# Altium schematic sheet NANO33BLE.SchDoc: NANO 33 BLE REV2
size A3; Date: 4/3/2020 11:51:50 AM; Author: Arturo Guadalupi; DocumentNumber: ABX00071/72; Revision: V6.3; SheetNumber: 1; SheetTotal: 1; Origin: Eagle; LibraryName: Arduino-utility; RevAuthor: Silvio Navaretti
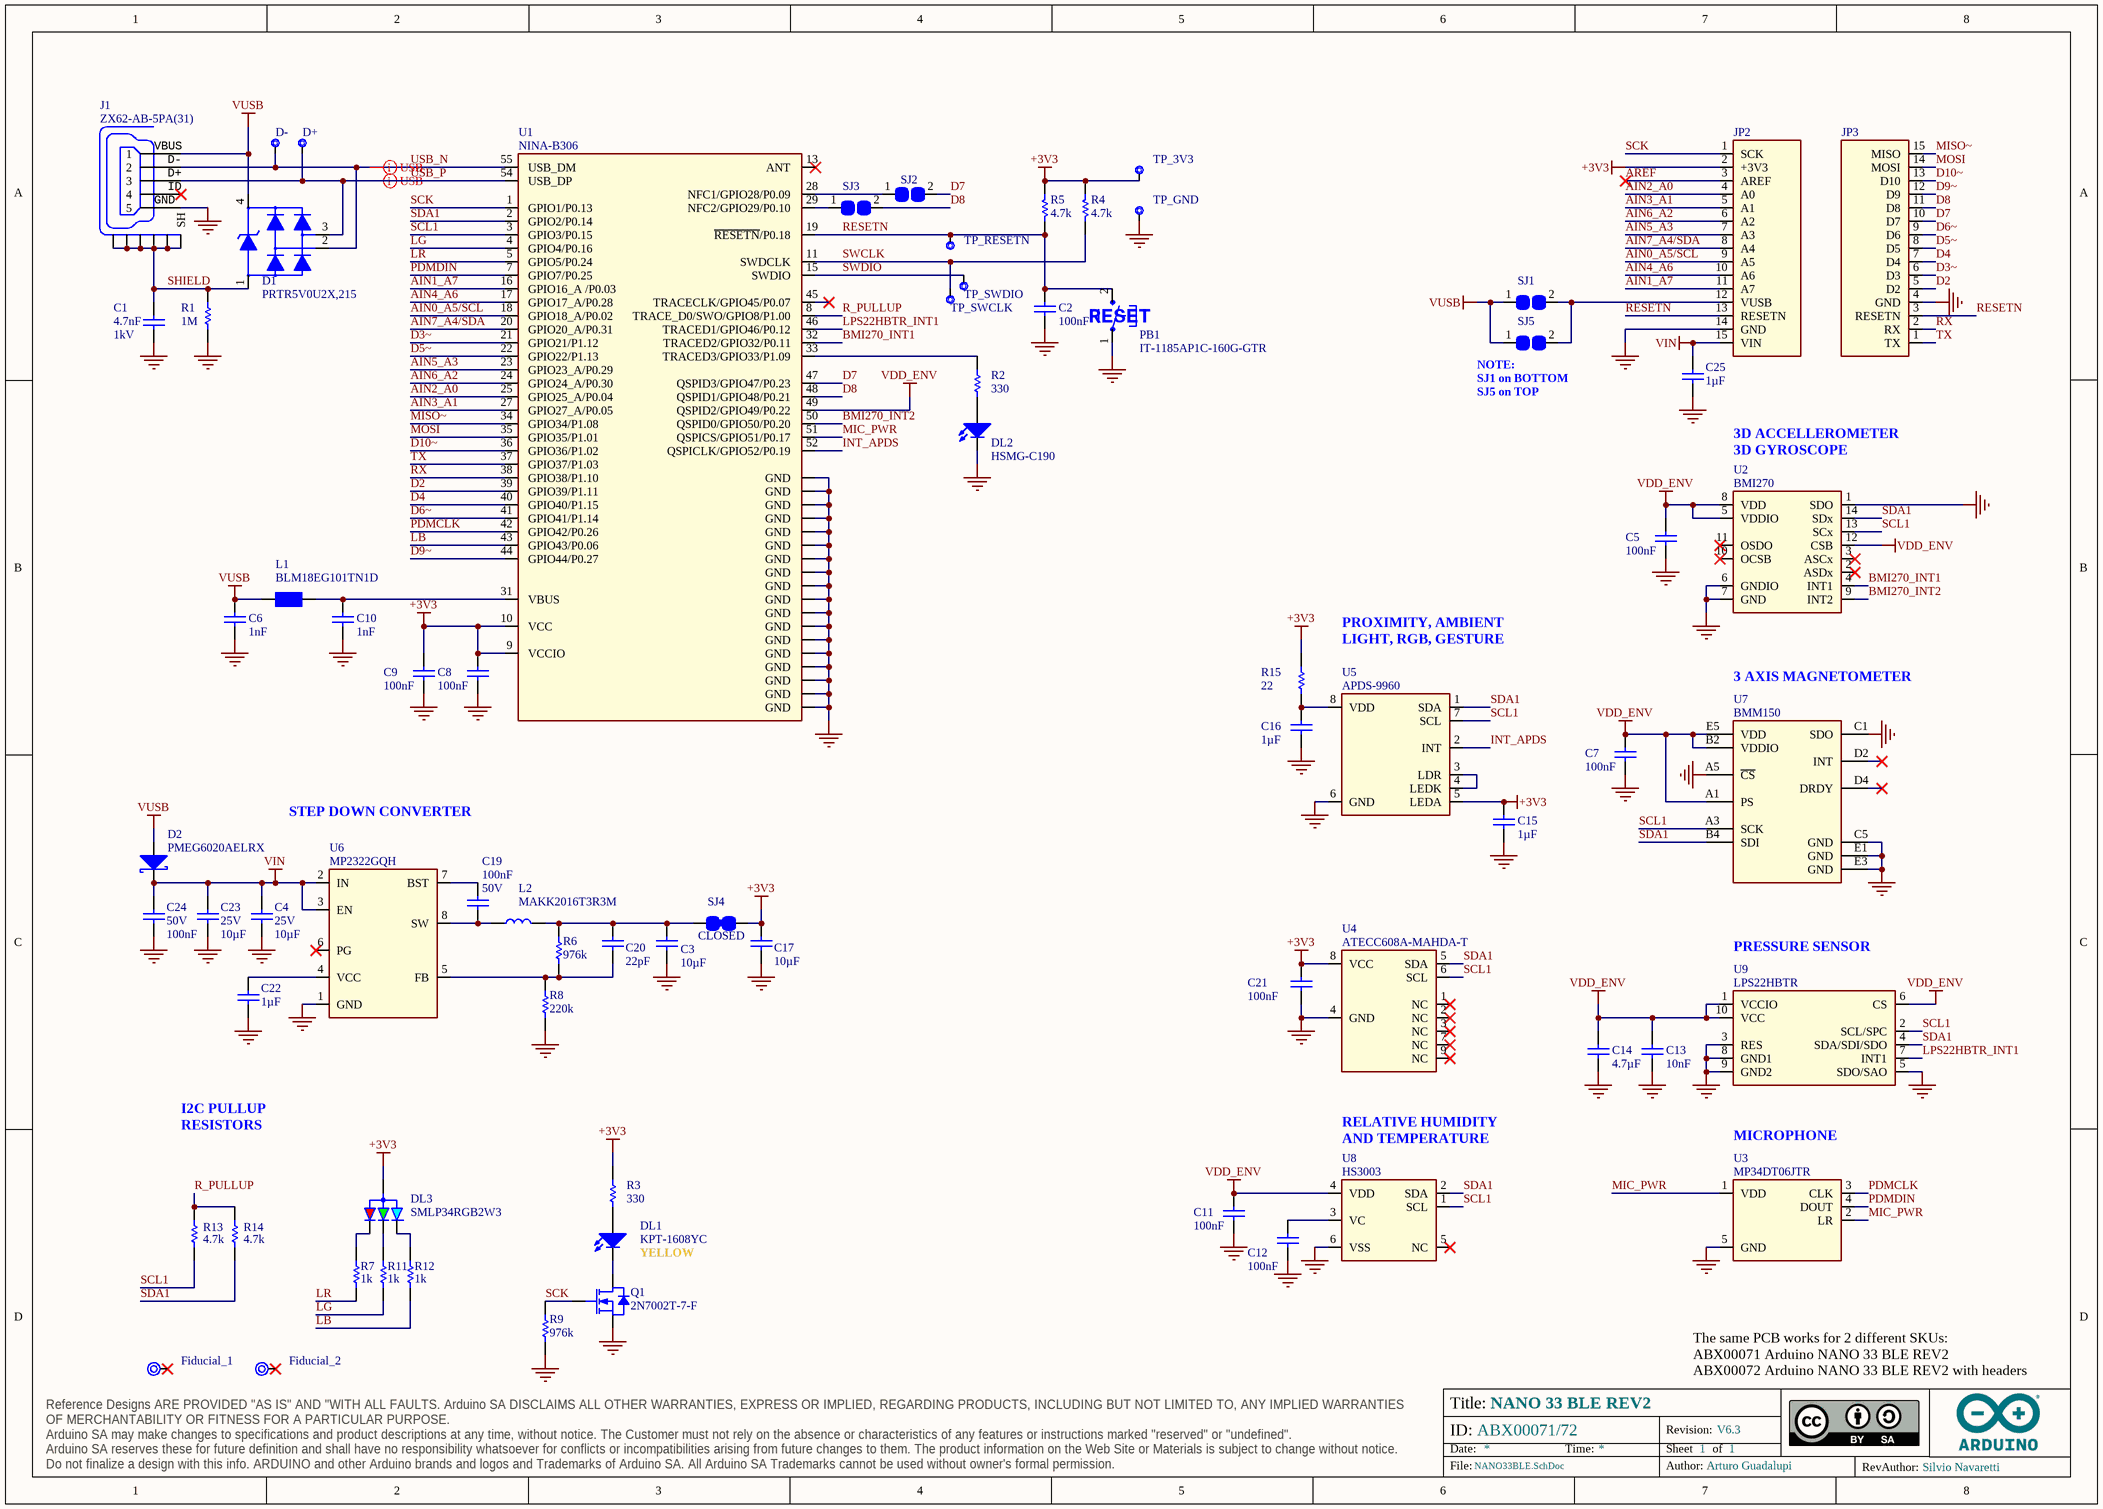
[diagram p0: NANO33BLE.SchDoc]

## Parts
C1  value 4.7nF  Voltage: 1kV  [CAP-0805]  (hidden comment: FV21X472K102ECG)
C2  value 100nF  [CAP-0402]  (hidden comment: GRM155R61H104KE19D)
C3  value 10µF  [CAP-0603]  (hidden comment: C1608A106M250NT)
C4  value 10µF  Voltage: 25V  [CAP-0603]  (hidden comment: C1608A106M250NT)
C5  value 100nF  [CAP-0402]  (hidden comment: 0402B104K160CT)
C6  value 1nF  [CAP-0402]  (hidden comment: GRM155R71H102KA01D)
C7  value 100nF  [CAP-0402]  (hidden comment: GRM155R61H104KE19D)
C8  value 100nF  [CAP-0402]  (hidden comment: GRM155R61H104KE19D)
C9  value 100nF  [CAP-0402]  (hidden comment: GRM155R61H104KE19D)
C10  value 1nF  [CAP-0402]  (hidden comment: GRM155R71H102KA01D)
C11  value 100nF  [CAP-0402]  (hidden comment: GRM155R61H104KE19D)
C12  value 100nF  [CAP-0402]  (hidden comment: GRM155R61H104KE19D)
C13  value 10nF  [CAP-0402]  (hidden comment: C1005B103K500NT)
C14  value 4.7µF  [CAP-0402]  (hidden comment: C1005A475M6R3NT)
C15  value 1µF  [CAP-0402]  (hidden comment: CL05A105KP5NNNC)
C16  value 1µF  [CAP-0402]  (hidden comment: CL05A105KP5NNNC)
C17  value 10µF  [CAP-0603]  (hidden comment: C1608A106M250NT)
C19  value 100nF  Voltage: 50V  [CAP-0402]  (hidden comment: GRM155R61H104KE19D)
C20  value 22pF  [CAP-0402]  (hidden comment: 0402N220J500CT)
C21  value 100nF  [CAP-0402]  (hidden comment: GRM155R61H104KE19D)
C22  value 1µF  [CAP-0402]  (hidden comment: CL05A105KP5NNNC)
C23  value 10µF  Voltage: 25V  [CAP-0603]  (hidden comment: C1608A106M250NT)
C24  value 100nF  Voltage: 50V  [CAP-0402]  (hidden comment: GRM155R61H104KE19D)
C25  value 1µF  [CAP-0402]  (hidden comment: CL05A105KP5NNNC)
D1  PRTR5V0U2X,215  [SOT190P230X110-4N]
D2  PMEG6020AELRX  [SOD123-1]
D+  CMP-018-0005-A.3  [TP-1.00MM]  (value not drawn)  (no BOM)
D-  CMP-018-0005-A.3  [TP-1.00MM]  (value not drawn)  (no BOM)
DL1  KPT-1608YC  [LEDC1608X80N-AK]
DL2  HSMG-C190  [LEDC1608X80N-AK]
DL3  SMLP34RGB2W3  [SMLP34RGB2W]
Fiducial_1  Fiducial mark 1mm with 2mm solder  [Fiducial mark 1mm with circle-Footprint-1]  (value not drawn)  (no BOM)
Fiducial_2  Fiducial mark 1mm with 2mm solder  [Fiducial mark 1mm with circle-Footprint-1]  (value not drawn)  (no BOM)
J1  ZX62-AB-5PA(31)  [ZX62-AB-5PA]
JP2  PINHD-1X15-NANO-ANALOG-CASTELLATED  [PINHD-1X14_5VF]  (value not drawn)
JP3  PINHD-1X15-NANO-DIGITAL-CASTELLATED  [PINHD-1X14_5VF]  (value not drawn)
L1  BLM18EG101TN1D  [L-0603]
L2  MAKK2016T3R3M  [MAKK2016T3R3M-Footprint-1]
PB1  IT-1185AP1C-160G-GTR  [C&K_PTS820_NO_HOLES-1]
Q1  2N7002T-7-F  [SOT523]
R1  value 1M  [RES-0402]  (hidden comment: CRCW04021M00FKED)
R2  value 330  [RES-0402]  (hidden comment: CRCW0402330RJNED)
R3  value 330  [RES-0402]  (hidden comment: CRCW0402330RJNED)
R4  value 4.7k  [RES-0402]  (hidden comment: RC0402FR-074K7L)
R5  value 4.7k  [RES-0402]  (hidden comment: RC0402FR-074K7L)
R6  value 976k  [RES-0402]  (hidden comment: CRCW0402976KFKED)
R7  value 1k  [RES-0402]  (hidden comment: CRCW04021K00FKEDC)
R8  value 220k  [RES-0402]  (hidden comment: CRCW0402220KFKED)
R9  value 976k  [RES-0402]  (hidden comment: CRCW0402976KFKED)
R11  value 1k  [RES-0402]  (hidden comment: CRCW04021K00FKEDC)
R12  value 1k  [RES-0402]  (hidden comment: CRCW04021K00FKEDC)
R13  value 4.7k  [RES-0402]  (hidden comment: RC0402FR-074K7L)
R14  value 4.7k  [RES-0402]  (hidden comment: RC0402FR-074K7L)
R15  value 22  [RES-0402]  (hidden comment: RC0402FR-0722RL)
SJ1  SMD solder JUMPER 0805  [SJ]  (value not drawn)
SJ2  SMD solder JUMPER 0805  [SJ]  (value not drawn)
SJ3  SMD solder JUMPER 0805  [SJ]  (value not drawn)
SJ4  SMD solder JUMPER CLOSED  [SJ]  (value not drawn)
SJ5  SMD solder JUMPER 0805  [SJ]  (value not drawn)
TP_3V3  CMP-018-0005-A.3  [TP-1.00MM]  (value not drawn)  (no BOM)
TP_GND  CMP-018-0005-A.3  [TP-1.00MM]  (value not drawn)  (no BOM)
TP_RESETN  CMP-018-0005-A.3  [TP-1.00MM]  (value not drawn)  (no BOM)
TP_SWCLK  CMP-018-0005-A.3  [TP-1.00MM]  (value not drawn)  (no BOM)
TP_SWDIO  CMP-018-0005-A.3  [TP-1.00MM]  (value not drawn)  (no BOM)
U1  NINA-B306  [NINA-B3X]
U2  BMI270  [VFLGA14]
U3  MP34DT06JTR  [HCLGA]
U4  ATECC608A-MAHDA-T  [UDFN8]
U5  APDS-9960  [APDS-9660-Footprint-1]
U6  MP2322GQH  [QFN50P150X200X90-8L]
U7  BMM150  [FP-BMM150-MFG]
U8  HS3003  [HS3003-Footprint-1]
U9  LPS22HBTR  [LPS22H]

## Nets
+3V3: C8.2 C9.1 C15.2 C17.2 C21.2 DL3.1(ANODE) JP2.2(+3V3) R3.2 R4.2 R5.2 R15.2 SJ4.2 TP_3V3.X U1.9(VCCIO) U1.10(VCC) U4.8(VCC) U5.5(LEDA)
GND: C1.1 C2.2 C3.1 C4.1 C5.2 C6.2 C7.1 C8.1 C9.2 C10.2 C11.2 C12.2 C13.2 C14.2 C15.1 C16.1 C17.1 C21.1 C22.1 C23.1 C24.2 C25.1 DL2.C J1.5 JP2.14(GND) JP3.4(GND) PB1.1 Q1.S R1.1 R8.1 R9.1 TP_GND.X U1.6(GND) U1.12(GND) U1.14(GND) U1.26(GND) U1.30(GND) U1.53(GND) U1.GND1(GND) U1.GND2(GND) U1.GND3(GND) U1.GND4(GND) U1.GND5(GND) U1.GND6(GND) U1.GND7(GND) U1.GND8(GND) U1.GND9(GND) U1.GND10(GND) U1.GND11(GND) U1.GND12(GND) U2.1(SDO) U2.6(GNDIO) U2.7(GND) U3.5(GND) U4.4(GND) U5.6(GND) U6.1(GND) U7.A5(~{CS}) U7.C1(SDO) U7.C5(GND) U7.E1(GND) U7.E3(GND) U8.6(VSS) U9.3(RES) U9.5(SDO/SAO) U9.8(GND1) U9.9(GND2)
VDD_ENV: C5.1 C7.2 C11.1 C13.1 C14.1 U1.49(QSPID2/GPIO49/P0.22) U2.5(VDDIO) U2.8(VDD) U2.12(CSB) U7.A1(PS) U7.B2(VDDIO) U7.E5(VDD) U8.4(VDD) U9.1(VCCIO) U9.6(CS) U9.10(VCC)
VIN: C4.2 C23.2 C24.1 C25.2 D2.C JP2.15(VIN) U6.2(IN) U6.3(EN)
VUSB: C6.1 D1.4 D2.A J1.1 L1.1 SJ1.1 SJ5.1
AIN0_A5/SCL: JP2.9(A5) U1.18(GPIO18_A/P0.02)
AIN1_A7: JP2.11(A7) U1.16(GPIO16_A_/P0.03)
AIN2_A0: JP2.4(A0) U1.25(GPIO25_A/P0.04)
AIN3_A1: JP2.5(A1) U1.27(GPIO27_A/P0.05)
AIN4_A6: JP2.10(A6) U1.17(GPIO17_A/P0.28)
AIN5_A3: JP2.7(A3) U1.23(GPIO23_A/P0.29)
AIN6_A2: JP2.6(A2) U1.24(GPIO24_A/P0.30)
AIN7_A4/SDA: JP2.8(A4) U1.20(GPIO20_A/P0.31)
AREF: JP2.3(AREF)
BMI270_INT1: U1.32(TRACED2/GPIO32/P0.11) U2.4(INT1)
BMI270_INT2: U1.50(QSPID0/GPIO50/P0.20) U2.9(INT2)
D2: JP3.5(D2) U1.39(GPIO39/P1.11)
D3~: JP3.6(D3) U1.21(GPIO21/P1.12)
D4: JP3.7(D4) U1.40(GPIO40/P1.15)
D5~: JP3.8(D5) U1.22(GPIO22/P1.13)
D6~: JP3.9(D6) U1.41(GPIO41/P1.14)
D7: JP3.10(D7) SJ2.2 U1.47(QSPID3/GPIO47/P0.23)
D8: JP3.11(D8) SJ3.2 U1.48(QSPID1/GPIO48/P0.21)
D9~: JP3.12(D9) U1.44(GPIO44/P0.27)
D10~: JP3.13(D10) U1.36(GPIO36/P1.02)
INT_APDS: U1.52(QSPICLK/GPIO52/P0.19) U5.2(INT)
LB: R12.1 U1.43(GPIO43/P0.06)
LG: R11.1 U1.4(GPIO4/P0.16)
LPS22HBTR_INT1: U1.46(TRACED1/GPIO46/P0.12) U9.7(INT1)
LR: R7.1 U1.5(GPIO5/P0.24)
MIC_PWR: U1.51(QSPICS/GPIO51/P0.17) U3.1(VDD) U3.2(LR)
MISO~: JP3.15(MISO) U1.34(GPIO34/P1.08)
MOSI: JP3.14(MOSI) U1.35(GPIO35/P1.01)
PDMCLK: U1.42(GPIO42/P0.26) U3.3(CLK)
PDMDIN: U1.7(GPIO7/P0.25) U3.4(DOUT)
R_PULLUP: R13.2 R14.2 U1.8(TRACE_D0/SWO/GPIO8/P1.00)
RESETN: C2.1 JP2.13(RESETN) JP3.3(RESETN) PB1.2 R5.1 TP_RESETN.X U1.19(~{RESETN}/P0.18)
RX: JP3.2(RX) U1.38(GPIO38/P1.10)
SCK: JP2.1(SCK) Q1.G R9.2 U1.1(GPIO1/P0.13)
SCL1: R13.1 U1.3(GPIO3/P0.15) U2.13(SCx) U4.6(SCL) U5.7(SCL) U7.A3(SCK) U8.1(SCL) U9.2(SCL/SPC)
SDA1: R14.1 U1.2(GPIO2/P0.14) U2.14(SDx) U4.5(SDA) U5.1(SDA) U7.B4(SDI) U8.2(SDA) U9.4(SDA/SDI/SDO)
SHIELD: C1.2 D1.1 J1.M1(SH) J1.M2(SH) J1.M3(SH) J1.M4(SH) J1.M5(SH) J1.M6(SH) R1.2
SWCLK: R4.1 TP_SWCLK.X U1.11(SWDCLK)
SWDIO: TP_SWDIO.X U1.15(SWDIO)
TX: JP3.1(TX) U1.37(GPIO37/P1.03)
USB_N: D1.2 D-.X J1.2 U1.55(USB_DM)
USB_P: D1.3 D+.X J1.3 U1.54(USB_DP)
NetC3_2: C3.2 C20.2 L2.2 R6.2 SJ4.1
NetC10_1: C10.1 L1.2 U1.31(VBUS)
NetC12_1: C12.1 U8.3(VC)
NetC16_2: C16.2 R15.1 U5.8(VDD)
NetC19_1: C19.1 L2.1 U6.8(SW)
NetC19_2: C19.2 U6.7(BST)
NetC20_1: C20.1 R6.1 R8.2 U6.5(FB)
NetC22_2: C22.2 U6.4(VCC)
NetDL1_A: DL1.A R3.1
NetDL1_C: DL1.C Q1.D
NetDL2_A: DL2.A R2.1
NetDL3_2: DL3.2(RED_C) R7.2
NetDL3_3: DL3.3(BLUE_C) R12.2
NetDL3_4: DL3.4(GREEN_C) R11.2
NetJP2_12: JP2.12(VUSB) SJ1.2 SJ5.2
NetR2_2: R2.2 U1.33(TRACED3/GPIO33/P1.09)
NetSJ2_1: SJ2.1 U1.28(NFC1/GPIO28/P0.09)
NetSJ3_1: SJ3.1 U1.29(NFC2/GPIO29/P0.10)
NetU5_3: U5.3(LDR) U5.4(LEDK)

Not connected (* = marked no-connect by the designer): Fiducial_1 1*; Fiducial_2 1*; J1 4*; U1 13(ANT)* 45(TRACECLK/GPIO45/P0.07)*; U2 2(ASDx)* 3(ASCx)* 10(OCSB)* 11(OSDO)*; U4 1(NC)* 2(NC)* 3(NC)* 7(NC)* 9(NC)*; U6 6(PG)*; U7 D2(INT)* D4(DRDY)*; U8 5(NC)*

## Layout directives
differential pair; differential pair class USB: USB_N, USB_P

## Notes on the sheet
- (near PB1) RESET
- (near SJ5) NOTE:
  SJ1 on BOTTOM
  SJ5 on TOP
- 3D ACCELLEROMETER
  3D GYROSCOPE
- PROXIMITY, AMBIENT LIGHT, RGB, GESTURE
- (near U7) 3 AXIS MAGNETOMETER
- STEP DOWN CONVERTER
- AUTHENTICATOR
- (near U9) PRESSURE SENSOR
- RGB LED
- SCK LED
- I2C PULLUP RESISTORS
- RELATIVE HUMIDITY
  AND TEMPERATURE
- MICROPHONE
- YELLOW
- The same PCB works for 2 different SKUs:
  ABX00071 Arduino NANO 33 BLE REV2
  ABX00072 Arduino NANO 33 BLE REV2 with headers

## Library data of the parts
C1 = C0059-A.14: CAP CHIP 0805 4.7nF 10% 1000V X7R; Manufacturer: PSA Shenzen; Code Arduino: 0689
C2 C7-C9 C11 C12 C19 C21 C24 = C0015-A.14: CAP CHIP 0402 100nF 10% 50V X5R; Manufacturer: Murata; Code Arduino: A5141
C3 C4 C17 C23 = C0047-A.18: CAP CHIP 0603 10uF 20% 25V X5R; Manufacturer: Hottech; Code Arduino: 2213
C5 = C0012-A.15: CAP CHIP 0402 100nF 10% 16V X7R; Manufacturer: Walsin; Code Arduino: 0132
C6 C10 = C0007-A.15: CAP CHIP 0402 1nF 10% 50V X7R; Manufacturer: KEMET; Code Arduino: 2321
C13 = C0009-A.15: CAP CHIP 0402 10nF 10% 50V X7R; Manufacturer: Hottech; Code Arduino: 0165
C14 = C0037-A.14: CAP CHIP 0402 4.7uF 20% 6V3 X5R; Manufacturer: Hottech; Code Arduino: 0833; Voltage: 6.3V
C15 C16 C22 C25 = C0017-A.14: CAP CHIP 0402 1uF 10% 10V X5R; Manufacturer: Samsung Electro-Mechanics; Code Arduino: 0133
C20 = C0029-A.14: CAP CHIP 0402 22pF 5% 50V C0G; Manufacturer: Walsin; Code Arduino: 0137
D1 = D0025-A.5: TVS ARRAY 4LIN.8kV 1pF SOT143B; Manufacturer: Nexperia; Device Type: ESD protection; Code Arduino: 2209
D2 = D0026-A.6: DIODE SCHOTTKY SMD 2A 60V SOD123FL; Manufacturer: Nexperia; Manucturer Part Number 2: SS26L; Code Arduino: 2208; Forward Voltage: 0.6V; Manucturer 2: Hottech
D+ D- TP_3V3 TP_GND TP_RESETN TP_SWCLK TP_SWDIO = UT0013-A.4: Test point 1.00mm
DL1 = L0008-A.5: LED SMD 0603 GIA588   8mcd 120^; Manufacturer: Kingbright; Code Arduino: 2243
DL2 = L0009-A.5: LED SMD 0603 GREEN/568 15mcd 120^; Manufacturer: Broadcom; Code Arduino: 2204
DL3 = L0014-A.11: LED RGB DIFFUSED PICOLED SMD; Manufacturer: ROHM Semiconductor; Code Arduino: A5469; Forward Current: 20mA; Lens Style: Rectangular; Dominant Wavelength: 470nm; Forward Voltage: 3V; Test Current: 5mA; Luminous Intensity: 45mcd; Lens Color: White
Fiducial_1 Fiducial_2 = UT0024-A.6
J1 = J0039-A.7: CONN USB MICRO F/90^ SMD TipoAB 5x1; Manufacturer: Hirose; Code Arduino: 2219
JP2 = J0158-A.4: CONN THD SOCKET F/1/D 15V JANALOG NANO-TYPE CASTELLATED; Code Arduino: 0646
JP3 = J0183-A.4: CONN THD SOCKET F/1/D 15V JDIGITAL NANO-TYPE CASTELLATED; Code Arduino: 0646
L1 = I0022-A.5: FERRITE SMD 0603 45mOHM 2A; Manufacturer: Murata; DC Resistance (DCR): 45mR; Test Frequency: 100MHz; Code Arduino: A5482; Tolerance: 25%
L2 = I0045-A.10: IND CHIP 0806 3.3 uH 20% 1.2A; Manufacturer: Taiyo Yuden; Max DC Current: 1.15A; Core Material: Metal; DC Resistance (DCR): 255mR; Code Arduino: I0045; Test Frequency: 2MHz; Inductance: 3.3µH; Shielding: Shielded; Value: 3.3µH
PB1 = B0001-A.7: PUSHBUTTON WHITE NO ANCHORS; Manufacturer: Switronic; Code Arduino: 0173
Q1 = T0003-A.2: MOSFET N-CH 60V 115mA SOT523; Manufacturer: Diodes Inc.; Device Type: Mosfet N-CH SMD; Code Arduino: 2368
R1 = R0058-A.24: RES CHIP 0402 1M 1% 1/16W; Manufacturer: Vishay; Power: 62.5mW; Code Arduino: 0139; Temperature coefficient: 100ppm
R2 R3 = R0017-A.24: RES CHIP 0402 330R 5% 1/16W; Manufacturer: Vishay; Power: 62.5mW; Code Arduino: 2229; Temperature coefficient: 200ppm
R4 R5 = R0013-A.24: RES CHIP 0402 4k7 1% 1/16W; Manufacturer: YAGEO; Code Arduino: 2196; Power: 62.5mW; Temperature coefficient: 200ppm
R6 R9 = R0070-A.25: RES CHIP 0402 976k 1% 1/16W; Manufacturer: Vishay; Power: 62.5mW; Code Arduino: R0070; Temperature coefficient: 100ppm
R7 R11 R12 = R0007-A.24: RES CHIP 0402 1k 1% 1/16W; Manufacturer: Vishay; Power: 62.5mW; Code Arduino: 0140; Temperature coefficient: 100ppm
R8 = R0028-A.24: RES CHIP 0402 220k 1% 1/16W; Manufacturer: Vishay; Code Arduino: 2334; Power: 62.5mW; Temperature coefficient: 200ppm
R13 R14 = R0013-A.24: RES CHIP 0402 4k7 1% 1/16W; Manufacturer: YAGEO; Power: 62.5mW; Code Arduino: 2196; Temperature coefficient: 200ppm
R15 = R0009-A.24: RES CHIP 0402 22R 1% 1/16W; Manufacturer: YAGEO; Power: 62.5mW; Code Arduino: 0468; Temperature coefficient: 100ppm
SJ1-SJ3 SJ5 = UT0002-A.5: Solder Jumper 0805 THIS IS NOT A COMPONENT
SJ4 = UT0006-A.14: Solder Jumper shorted pads. This is not a component
U1 = M0001-A.9: MODULE BLE 5.0 STAND ALONE nRF52; Manufacturer: UBlox
U2 = U0217-A.4: IC IMU 6 AXIS 14VFLGA pin to pin alternative to LSM6DSOXTR; Manufacturer: Bosch Sensortec; Code Arduino: U0217
U3 = U0074-A.6: SENS MEMS AUDIO OMNIDIRECTIONAL; Manufacturer: ST Microelectronics; Code Arduino: A5470
U4 = U0034-A.8: IC AUTHENTICATION CHIP UDFN8; Manufacturer: Microchip; Code Arduino: U0034
U5 = U0136-A.9: IC SENS OPT 560NM AMBIENT MODULE APDS-9960; Manufacturer: Broadcom; Code Arduino: A5475
U6 = U0072-A.8: IC STEP DOWN CONV 1A 22V QFN8; Manufacturer: Monolithic Power Systems; Code Arduino: U0072
U7 = U0153-A.4: IC SENSOR 3-AXIS GEOMAGNETIC; Manufacturer: Bosch Sensortec; Code Arduino: U0153
U8 = U0253-A.5: IC PRESSURE AND TEMPERATURE SENSOR 6-LGA; Manufacturer: Renesas; Code Arduino: U0253
U9 = U0009-A.7: SENSOR PRESSURE 3.77 PSI ~ 18.27 PSI (26 kPa ~ 126 kPa) Absolute 24 b 10-WFLGA; Manufacturer: ST Microelectronics; Code Arduino: A5390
